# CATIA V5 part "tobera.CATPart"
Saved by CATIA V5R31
Part number: tobera
Bounding box of the stored display mesh (mm): x -52.663 to 52.5, y -61.5 to 61.5, z -74.554 to 40
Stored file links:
  C:\Users\189361\Desktop\comedero, planos\tobera.CATPart
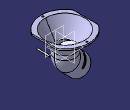
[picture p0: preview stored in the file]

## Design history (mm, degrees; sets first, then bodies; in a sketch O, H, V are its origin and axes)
Set1 "sketch"
  Sketch1 on xy-plane, origin (0, 0, 0), H (1, 0, 0), V (0, 1, 0)
    line L1 (52.5, 61.5) -> (52.5, -61.5)
    line L2 (52.5, -61.5) -> (-52.5, -61.5)
    line L3 (-52.5, -61.5) -> (-52.5, 61.5)
    line L4 (-52.5, 61.5) -> (52.5, 61.5)
    length L4 = 105
    length L1 = 123
    vertical: L1 V, L3 V
    horizontal: L2 H, L4 H
    equidistance: L1 L3 O, L2 L4 O
  Sketch2 on yz-plane, origin (0, 0, 0), H (0, 1, 0), V (0, 0, 1)
    point P1 (0, 0)
    line L1 (0, 0) -> (25, 0)
    line L2 (25, 0) -> (50, 40)
    line L3 (50, 40) -> (0, 40)
    point P4 (0, 40)
    reference projected line E1 (-61.5, 40) -> (61.5, 40) from edge [face of Pad1 from Sketch1.L1 | end face of Pad1]
    length L1 = 25
    length L3 = 50
    coincidence: P1 H, P4 V, P1 V, L3 E1
    horizontal: L1 H, L3 H
  Sketch3 on start face of Pad1, origin (0, 0, 0), H (1, 0, 0), V (0, -1, 0)
    circle A1 centre (0, 0) radius 26.5
    radius A1 = 26.5
  Sketch4 on face of Rib1, origin (0, 0, 0), H (1, 0, 0), V (0, 1, 0)
    circle A1 centre (0, 0) radius 25
    radius A1 = 25
  Sketch5 on end face of Pad1, origin (0, 0, 40), H (1, 0, 0), V (0, 1, 0)
    circle A1 centre (0, -56) radius 2.25
    point P1 (0, -56)
    reference projected line E1 through (0, 0) direction (1, 0) from axis of face of Slot1
    circle A2 centre (0, 56) radius 2.25
    radius A1 = 2.25
    distance P1 H = 56
    coincidence: P1 V
    symmetry: A1 A2 E1
  Sketch6 on yz-plane, origin (0, 0, 0), H (0, 1, 0), V (0, 0, 1)
    point P1 (26.5, 0)
    point P2 (50.35, 36)
    line L1 (61.5, 36) -> (61.5, 0)
    point P4 (61.5, 0)
    line L2 (61.5, 0) -> (26.5, 0)
    reference projected line E1 (61.5, 0) -> (61.5, 40) from edge [face of Pad1 from Sketch1.L3 | face of Pad1 from Sketch1.L4]
    line L3 (50.35, 36) -> (61.5, 36)
    reference projected line E2 (61.5, 40) -> (-61.5, 40) from edge [face of Pad1 from Sketch1.L3 | end face of Pad1]
    construction line L4 (0, 40) -> (53, 40)
    point P5 (0, 40)
    point P6 (53, 40)
    reference projected line E3 (-50, 40) -> (50, 40) from edge [end face of Pad1 | face of Groove1 from Sketch2.L2]
    axis line L5 (26.5, 0) -> (53, 40)
    line L6 (26.5, 0) -> (50.35, 36)
    distance P1 V = 26.5
    distance L3 E2 = 4
    distance P6 P5 = 53
    coincidence: P1 H, P4 H, E1 L1, P5 V, E3 L4, P2 L5
    vertical: L1 V
    horizontal: L2 H, L3 H, L4 H
  Sketch7 on start face of Pad1, origin (0, 0, 0), H (1, 0, 0), V (0, -1, 0)
  Sketch8 on zx-plane, origin (0, 0, 0), H (-1, 0, 0), V (0, 0, 1)
    arc A1 centre (19.7825, -41.6735) radius 2.8 from (17.8026, -39.6936) to (21.7624, -43.6534) ccw
    point P1 (19.7825, -41.6735)
    line L1 (17.8026, -39.6936) -> (36.5409, -20.9553)
    line L2 (36.5409, -20.9553) -> (40.5007, -24.9151)
    line L3 (40.5007, -24.9151) -> (21.7624, -43.6534)
    reference projected line E1 (9.1759, -31.0669) -> (32.5104, -54.4014) from Sketch11.L2
    reference projected point E2 (33.9246, -55.8156) from Sketch11.P4
    radius A1 = 2.8
    length L3 = 26.5
    distance E2 P1 = 20
    perpendicularity: L2 L1
    parallelism: L3 L1, L2 E1
    tangency: A1 L3, A1 L1
    coincidence: P1 E1
  Sketch9 on Plane1, origin (0, -26.5, 0), H (-1, 0, 0), V (0, 0, 1)
    construction line L1 (38.1673, -45.9161) -> (24.0251, -60.0583)
    construction line L2 (24.0251, -60.0583) -> (-14.1586, -21.8745)
    point P3 (-14.1586, -21.8745)
    construction line L3 (38.1673, -45.9161) -> (-0.0165, -7.7324)
    point P4 (38.1673, -45.9161)
    axis line L4 (-14.1586, -21.8745) -> (-0.0165, -7.7324)
    point P6 (-14.1586, -21.8745)
    construction circle A1 centre (19.7825, -41.6735) radius 3
    point P7 (19.7825, -41.6735)
    reference projected line E1 (9.1759, -31.0669) -> (32.5104, -54.4014) from Sketch11.L2
    reference projected arc E2 centre (19.7825, -41.6735) radius 2.8 from (17.8026, -39.6936) to (21.7624, -43.6534) ccw from edge [face of Pocket3 from Sketch8.A1 | face of Rib1]
    line L5 (40.6421, -48.391) -> (38.5208, -46.2697)
    line L6 (38.5208, -46.2697) -> (24.0251, -60.7654)
    line L7 (24.0251, -60.7654) -> (-14.5122, -22.2281)
    line L8 (-14.5122, -22.2281) -> (-16.6335, -24.3494)
    line L9 (-16.6335, -24.3494) -> (24.0251, -65.008)
    line L10 (24.0251, -65.008) -> (40.6421, -48.391)
    line L11 (2.4584, -5.2575) -> (9.5294, -12.3286)
    line L12 (9.5294, -12.3286) -> (7.4081, -14.4499)
    line L13 (7.4081, -14.4499) -> (0.3371, -7.3788)
    line L14 (0.3371, -7.3788) -> (2.4584, -5.2575)
    length L3 = 54
    length L4 = 20
    radius A1 = 3
    distance L1 P7 = 16
    distance P7 L2 = 10
    length L8 = 3
    length L5 = 3
    distance L6 L1 = 0.5
    distance L7 L2 = 0.5
    distance L13 L11 = 3
    length L11 = 10
    distance L3 L13 = 0.5
    coincidence: P4 L1, P3 P6, L5 L3, L8 L4, L14 L4
    parallelism: L4 L1, L2 L3, L3 E1, L5 L2, L7 L5, L8 L1, L9 L7, L10 L1, L11 L9, L12 L4, L14 L4
    perpendicularity: L1 L2, L12 L13
    concentricity: A1 E2
  Sketch10 on zx-plane, origin (0, 0, 0), H (-1, 0, 0), V (0, 0, 1)
    line L1 (10.0455, -12.0981) -> (25, -3.4641)
    point P2 (25, -3.4641)
    line L2 (25, -3.4641) -> (25, 0)
    point P3 (25, 0)
    line L3 (25, 0) -> (8.5455, -9.5)
    line L4 (8.5455, -9.5) -> (10.0455, -12.0981)
    distance P3 V = 25
    distance P2 V = 25
    distance P3 H = 0
    length L4 = 3
    length L3 = 19
    angle L3 L2 = 60
    parallelism: L3 L1
    perpendicularity: L4 L1
Set2 "planos"
  Plane1: type Offset, RefPlane zx-plane, Offset 26.5, reversed
Set3 "lineas"
  Sketch11 on zx-plane, origin (0, 0, 0), H (-1, 0, 0), V (0, 0, 1)
    line L1 (0, 0) -> (0, -10.9144)
    point P1 (0, -3.3)
    point P4 (33.9246, -55.8156)
    line L2 (33.9246, -55.8156) -> (7.7617, -29.6527)
    reference projected line E1 (52.5, 0) -> (52.5, 40) from edge [face of Pad1 from Sketch1.L3 | face of Pad1 from Sketch1.L4]
    arc A1 centre (26.5, -10.9144) radius 26.5 from (0, -10.9144) to (7.7617, -29.6527) ccw
    reference projected line E2 (-52.5, 0) -> (52.5, 0) from edge [start face of Pad1 | face of Pad1 from Sketch1.L4]
    distance O P1 = 3.3
    angle L2 E1 = 45
    length L2 = 37
    radius A1 = 26.5
    distance P4 E2 = 55.8156
    vertical: L1 V
    coincidence: L1 P1
    tangency: A1 L1, L2 A1
Body1 (main body)
  Pad1: profile Sketch1, direction (0, 0, 1), length 40
  Groove1: profile Sketch2, axis Sketch2.V, angle 360
  Rib1: profile Sketch3, centre curve Sketch11
  Slot1: profile Sketch4, centre curve Sketch11
  Pocket1: profile Sketch5, direction (0, 0, -1), through (limit type 6)
  Groove2: profile Sketch6, axis Sketch6.V, angle 360
  Pocket2: profile Sketch7, direction (0, 0, 1), through (limit type 6)
  Pocket3: profile Sketch8, direction (0, -1, 0), through (limit type 6), opposite side through (limit type 6)
  Pad2: profile Sketch9, direction (0, 1, 0), up to the existing solid (limit type 2), opposite side length 30
  Fillet1: radius 5, on edge [face of Pad2 from Sketch9.L11 | face of Rib1]; edge [face of Rib1 | face of Pad2 from Sketch9.L9]; edge [face of Pad2 from Sketch9.L9 | face of Rib1]; edge [face of Pad2 from Sketch9.L14 | face of Rib1]; edge [face of Rib1 | face of Pad2 from Sketch9.L8]; edge [face of Rib1 | face of Pad2 from Sketch9.L12]
  Pad3: profile Sketch10, direction (0, 1, 0), up to the existing solid (limit type 2), opposite side up to the existing solid (limit type 2)
  Fillet2: radius 1.5, on edge [face of Pad3 from Sketch10.L4 | face of Pad3 from Sketch10.L3]; edge [face of Pad3 from Sketch10.L1 | face of Pad3 from Sketch10.L4]
  Fillet3: radius 1.5, on edge [face of Pad2 from Sketch9.L5 | face of Rib1]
